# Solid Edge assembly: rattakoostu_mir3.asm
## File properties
Author: Türk
Template: Iso Assembly.asm
Last saved by: Türk
Revision: 3
Application: Solid Edge
Username: Türk
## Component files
VlegR18_2_mir3.par
Rehv.par
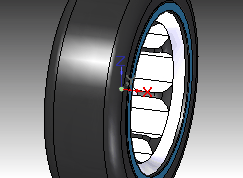
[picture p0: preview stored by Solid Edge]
